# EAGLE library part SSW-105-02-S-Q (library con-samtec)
THROUGH-HOLE .025" SQ POST SOCKET Source: Samtec SSW.pdf
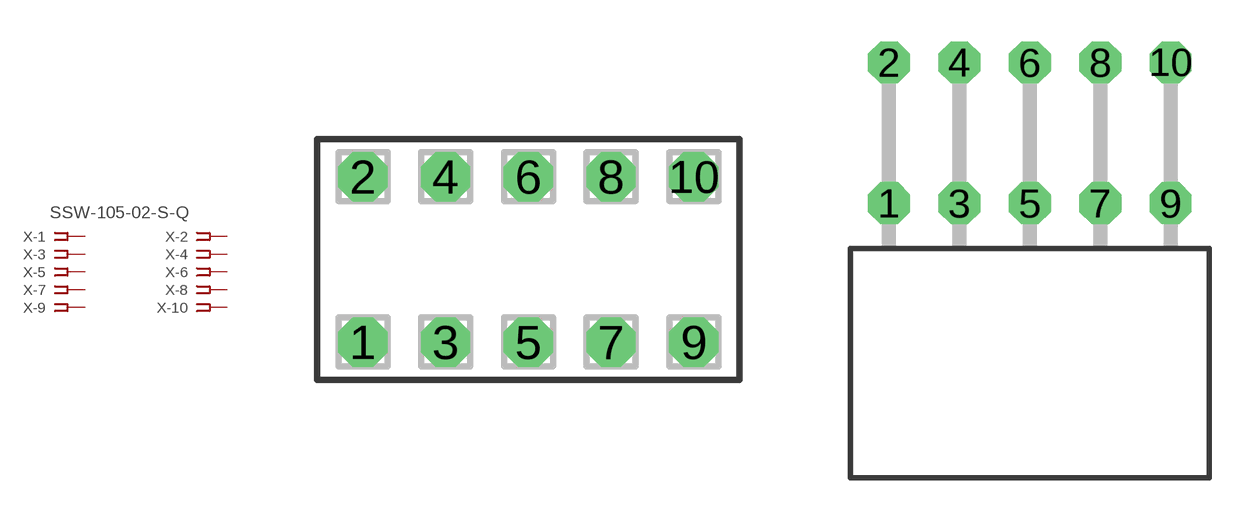
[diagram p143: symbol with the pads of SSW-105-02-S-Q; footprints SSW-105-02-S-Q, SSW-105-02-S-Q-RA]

Designator prefix X; gates -1=FPINV -2=FPIN -3=FPIN -4=FPIN -5=FPIN -6=FPIN -7=FPIN -8=FPIN -9=FPIN -10=FPIN

## SSW-105-02-S-Q (MPN: SSW-105-02-S-Q; OC_FARNELL: unknown; OC_NEWARK: 82P2928)  [SSW-105-02-S-Q]
1  -1:1  pas
2  -2:1  pas
3  -3:1  pas
4  -4:1  pas
5  -5:1  pas
6  -6:1  pas
7  -7:1  pas
8  -8:1  pas
9  -9:1  pas
10  -10:1  pas

## SSW-105-02-S-QRA (MPN: SSW-105-02-S-Q-RA; OC_FARNELL: unknown; OC_NEWARK: 82P2929)  [SSW-105-02-S-Q-RA]
Pads as for SSW-105-02-S-Q

## Footprint SSW-105-02-S-Q (pad centres in mm)
THROUGH-HOLE .025" SQ POST SOCKET Source: Samtec SSW.pdf
drill 1 pad 1.5 octagon: 1 -5.08,-2.54; 2 -5.08,2.54; 3 -2.54,-2.54; 4 -2.54,2.54; 5 0,-2.54; 6 0,2.54; 7 2.54,-2.54; 8 2.54,2.54; 9 5.08,-2.54; 10 5.08,2.54

## Footprint SSW-105-02-S-Q-RA (pad centres in mm)
THROUGH-HOLE .025" SQ POST SOCKET Source: Samtec SSW.pdf
drill 1 pad 1.5 octagon: 1 -5.08,1.524; 2 -5.08,6.604; 3 -2.54,1.524; 4 -2.54,6.604; 5 0,1.524; 6 0,6.604; 7 2.54,1.524; 8 2.54,6.604; 9 5.08,1.524; 10 5.08,6.604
